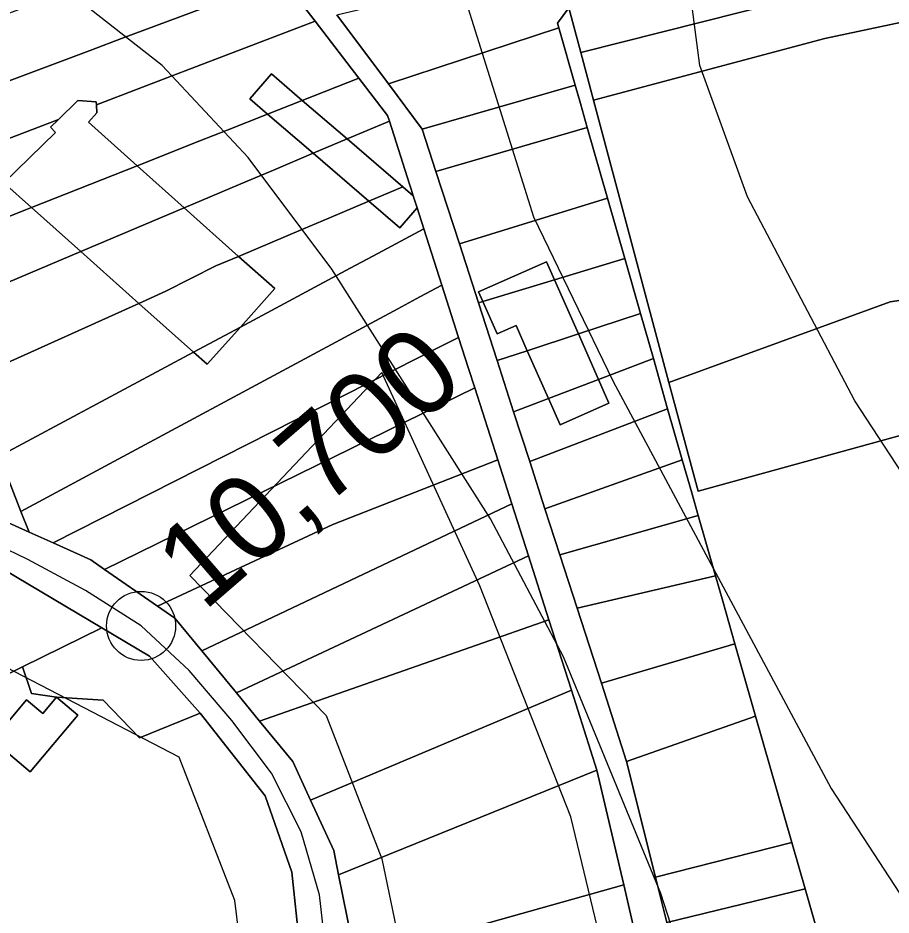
# Model space of a CAD drawing. Extents: x -510989 to -501240, y -1184665 to -1176098.
# Drawn here: x -509285.3 to -509152.5, y -1180014.3 to -1179877.8 of the extents above; entities that cross this region are included whole.
import ezdxf

# ---------------------------------------------------------------- set-up
doc = ezdxf.new("R2010")
doc.units = 0
for name, color, linetype in [('ostatni_plocha_x_manipulacni_plocha', 7, 'Continuous'), ('STAV_systematicke_odvodneni', 7, 'Continuous'), ('trasovani_toku', 7, 'Continuous'), ('trvaly_travni_porost', 7, 'Continuous'), ('vodni_plocha_x_vodni_tok_v_koryte_umelem', 7, 'Continuous'), ('vrstevnice_01', 7, 'Continuous'), ('vrstevnice_02', 7, 'Continuous'), ('zastavena_plocha_a_nadvori', 7, 'Continuous')]:
    doc.layers.add(name, color=color, linetype=linetype)

msp = doc.modelspace()

# ---------------------------------------------------------------- linework, layer by layer
at = {"layer": 'ostatni_plocha_x_manipulacni_plocha'}
for points in [[(-509245.12, -1179871.74), (-509269.59, -1179880.91), (-509274.08, -1179882.59), (-509299.47, -1179892.1), (-509300.3, -1179891.36), (-509292.23, -1179882.25), (-509294.72, -1179880.05), (-509282.51, -1179875.46), (-509277.9, -1179873.72), (-509251.28, -1179863.71)], [(-509194.72, -1179867.22), (-509198.47, -1179872.21), (-509201.5, -1179876.24), (-509203.25, -1179878.55), (-509203.04, -1179879.28), (-509228.95, -1179887.79), (-509236.79, -1179877.28)], [(-509240.13, -1179878.24), (-509262.69, -1179886.88), (-509267.04, -1179888.55), (-509273.41, -1179890.99), (-509273.44, -1179890.5), (-509276.22, -1179890.32), (-509279.16, -1179893.19), (-509338.41, -1179915.88), (-509354.67, -1179922.9), (-509366.26, -1179917.12), (-509299.47, -1179892.1), (-509274.08, -1179882.59), (-509269.59, -1179880.91), (-509245.12, -1179871.74)], [(-509262.69, -1179886.88), (-509240.13, -1179878.24), (-509233.49, -1179886.9), (-509242.08, -1179890.3), (-509246.77, -1179886.28), (-509250.04, -1179890.09), (-509247.36, -1179892.39), (-509253.51, -1179894.83), (-509257.67, -1179896.48), (-509267.21, -1179900.25), (-509274.62, -1179893.63), (-509273.33, -1179892.18), (-509273.41, -1179890.99), (-509267.04, -1179888.55)], [(-509228.95, -1179887.79), (-509203.04, -1179879.28), (-509200.54, -1179888), (-509223.83, -1179894.66)], [(-509242.08, -1179890.3), (-509233.49, -1179886.9), (-509229.09, -1179892.63), (-509228.82, -1179893.47), (-509235.24, -1179896.18)], [(-509200.54, -1179888), (-509199.75, -1179890.78), (-509198.71, -1179894.43), (-509221.74, -1179901.11), (-509223.83, -1179894.66)], [(-509253.51, -1179894.83), (-509247.36, -1179892.39), (-509240.41, -1179898.36), (-509246.46, -1179900.92), (-509250.44, -1179902.6), (-509260.03, -1179906.66), (-509267.21, -1179900.25), (-509257.67, -1179896.48)], [(-509279.16, -1179893.19), (-509280.4, -1179894.4), (-509279.63, -1179895.2), (-509287.49, -1179902.86), (-509283.28, -1179906.61), (-509298.86, -1179912.78), (-509345.31, -1179927.56), (-509354.67, -1179922.9), (-509338.41, -1179915.88)], [(-509235.24, -1179896.18), (-509228.82, -1179893.47), (-509225.76, -1179903.05), (-509225.52, -1179903.8), (-509225.19, -1179904.81), (-509226.76, -1179903.47)], [(-509221.74, -1179901.11), (-509198.71, -1179894.43), (-509195.63, -1179905.19), (-509218.17, -1179912.14)], [(-509246.46, -1179900.92), (-509240.41, -1179898.36), (-509231.92, -1179905.65), (-509238.01, -1179908.23), (-509241.87, -1179909.86), (-509251.76, -1179914.04), (-509260.03, -1179906.66), (-509250.44, -1179902.6)], [(-509238.01, -1179908.23), (-509231.92, -1179905.65), (-509227.22, -1179909.7), (-509224.6, -1179906.65), (-509223.58, -1179909.86), (-509231.33, -1179914.01), (-509234.78, -1179915.86), (-509251.49, -1179924.79), (-509246.27, -1179918.94), (-509251.76, -1179914.04), (-509241.87, -1179909.86)], [(-509218.17, -1179912.14), (-509195.63, -1179905.19), (-509193, -1179914.38), (-509203.69, -1179917.62), (-509204.89, -1179914.88), (-509215.25, -1179919.45), (-509214.6, -1179920.92), (-509215.27, -1179921.12)], [(-509298.86, -1179912.78), (-509283.28, -1179906.61), (-509275.78, -1179913.31), (-509296.5, -1179922.05), (-509334.69, -1179932.64), (-509345.31, -1179927.56)], [(-509231.33, -1179914.01), (-509223.58, -1179909.86), (-509220.84, -1179918.43), (-509224.16, -1179920.21), (-509227.51, -1179922.01), (-509284.89, -1179952.84), (-509288.21, -1179944.42), (-509258.64, -1179928.61), (-509256.56, -1179930.46), (-509251.49, -1179924.79), (-509234.78, -1179915.86)], [(-509275.78, -1179913.31), (-509266.94, -1179921.2), (-509289.06, -1179931.17), (-509314.67, -1179934.24), (-509322.46, -1179933.61), (-509334.69, -1179932.64), (-509296.5, -1179922.05)], [(-509203.69, -1179917.62), (-509193, -1179914.38), (-509190.61, -1179922.72), (-509200.06, -1179925.84)], [(-509224.16, -1179920.21), (-509220.84, -1179918.43), (-509218.29, -1179926.38), (-509220.83, -1179927.67), (-509280, -1179957.64), (-509283.64, -1179956), (-509284.89, -1179952.84), (-509227.51, -1179922.01)], [(-509266.94, -1179921.2), (-509258.64, -1179928.61), (-509288.21, -1179944.42), (-509287.28, -1179937.97), (-509311.6, -1179934.48), (-509314.67, -1179934.24), (-509289.06, -1179931.17)], [(-509215.27, -1179921.12), (-509214.6, -1179920.92), (-509212.43, -1179925.82), (-509209.53, -1179924.54), (-509207.83, -1179928.4), (-509212.43, -1179929.91)], [(-509200.06, -1179925.84), (-509190.61, -1179922.72), (-509188.65, -1179929.58), (-509196.99, -1179932.77)], [(-509220.83, -1179927.67), (-509218.29, -1179926.38), (-509216.78, -1179931.09), (-509215.83, -1179934.07), (-509272.16, -1179961.67), (-509274.23, -1179960.24), (-509280, -1179957.64)], [(-509212.43, -1179929.91), (-509207.83, -1179928.4), (-509204.61, -1179935.68), (-509209.91, -1179937.7)], [(-509196.99, -1179932.77), (-509188.65, -1179929.58), (-509186.47, -1179937.23), (-509207.46, -1179945.27), (-509209.91, -1179937.7), (-509204.61, -1179935.68), (-509202.85, -1179939.66), (-509195.4, -1179936.37)], [(-509311.6, -1179934.48), (-509287.28, -1179937.97), (-509288.21, -1179944.42), (-509284.89, -1179952.84), (-509283.64, -1179956), (-509308.5, -1179944.81)], [(-509212.33, -1179945), (-509237.41, -1179954.86), (-509264.12, -1179967.25), (-509272.16, -1179961.67), (-509215.83, -1179934.07)], [(-509186.47, -1179937.23), (-509184.24, -1179945.01), (-509205.14, -1179952.44), (-509207.46, -1179945.27)], [(-509210.2, -1179951.69), (-509257.36, -1179974.08), (-509261.47, -1179969.08), (-509264.12, -1179967.25), (-509237.41, -1179954.86), (-509212.33, -1179945)], [(-509184.24, -1179945.01), (-509182.8, -1179950.04), (-509181.82, -1179953.46), (-509202.87, -1179959.47), (-509205.14, -1179952.44)], [(-509308.37, -1179951.14), (-509303.03, -1179953.6), (-509289.24, -1179960.67), (-509272.59, -1179970.58), (-509284.66, -1179976.49), (-509289.12, -1179978.67), (-509294.14, -1179974.39), (-509290.6, -1179970.25), (-509297.99, -1179963.94), (-509301.31, -1179967.84), (-509303.11, -1179962.06)], [(-509207.66, -1179959.6), (-509252.09, -1179980.48), (-509257.36, -1179974.08), (-509210.2, -1179951.69)], [(-509202.87, -1179959.47), (-509181.82, -1179953.46), (-509179.19, -1179962.66), (-509200.25, -1179967.55)], [(-509204.54, -1179969.37), (-509248.57, -1179984.76), (-509252.09, -1179980.48), (-509207.66, -1179959.6)], [(-509179.19, -1179962.66), (-509178.09, -1179966.51), (-509176.23, -1179972.99), (-509196.56, -1179978.97), (-509200.25, -1179967.55)], [(-509272.59, -1179970.58), (-509265.34, -1179974.89), (-509257.62, -1179983.54), (-509266.85, -1179987.32), (-509272.39, -1179981.57), (-509279.49, -1179981.11), (-509283.26, -1179980.55), (-509284.66, -1179976.49)], [(-509201.12, -1179980.06), (-509240.8, -1179996.81), (-509243.51, -1179990.9), (-509248.57, -1179984.76), (-509204.54, -1179969.37)], [(-509196.56, -1179978.97), (-509176.23, -1179972.99), (-509173.08, -1179984), (-509192.71, -1179990.88)], [(-509283.26, -1179980.55), (-509279.49, -1179981.11), (-509281.57, -1179983.59), (-509284.05, -1179981.5), (-509289.22, -1179987.65), (-509283.48, -1179992.48), (-509276.22, -1179983.86), (-509279.49, -1179981.11), (-509272.39, -1179981.57), (-509266.85, -1179987.32), (-509257.62, -1179983.54), (-509247.71, -1179996.14), (-509243.68, -1180007.74), (-509242.47, -1180018.79), (-509284.8, -1180026.46), (-509292.2, -1180004.67), (-509287.42, -1179999.06), (-509291.8, -1179995.32), (-509294.36, -1179998.32), (-509297.64, -1179988.66), (-509294.4, -1179984.86), (-509289.12, -1179978.67), (-509284.66, -1179976.49)], [(-509197.23, -1179992.2), (-509236.54, -1180008.14), (-509237.28, -1180004.46), (-509240.8, -1179996.81), (-509201.12, -1179980.06)], [(-509192.71, -1179990.88), (-509173.08, -1179984), (-509167.57, -1180003.21), (-509188.32, -1180008.48)], [(-509197.23, -1179992.2), (-509193.16, -1180009.68), (-509233.9, -1180021.14), (-509236.54, -1180008.14)], [(-509188.32, -1180008.48), (-509167.57, -1180003.21), (-509165.54, -1180010.3), (-509186.6, -1180015.39)], [(-509191.41, -1180017.18), (-509234.79, -1180031.74), (-509233.9, -1180021.14), (-509193.16, -1180009.68)], [(-509186.6, -1180015.39), (-509165.54, -1180010.3), (-509163.91, -1180015.98), (-509185.17, -1180021.13)]]:
    msp.add_lwpolyline(points, close=True, dxfattribs=at)
for points in [[(-509191.41, -1180017.18), (-509193.16, -1180009.68), (-509197.23, -1179992.2), (-509201.12, -1179980.06), (-509204.54, -1179969.37), (-509207.66, -1179959.6), (-509210.2, -1179951.69), (-509212.33, -1179945), (-509215.83, -1179934.07), (-509216.78, -1179931.09), (-509218.29, -1179926.38), (-509220.84, -1179918.43), (-509223.58, -1179909.86), (-509224.6, -1179906.65), (-509225.19, -1179904.81), (-509225.52, -1179903.8), (-509225.76, -1179903.05), (-509228.82, -1179893.47), (-509229.09, -1179892.63), (-509233.49, -1179886.9), (-509240.13, -1179878.24), (-509245.12, -1179871.74)], [(-509236.79, -1179877.28), (-509228.95, -1179887.79), (-509223.83, -1179894.66), (-509221.74, -1179901.11), (-509218.17, -1179912.14), (-509215.27, -1179921.12), (-509212.43, -1179929.91), (-509209.91, -1179937.7), (-509207.46, -1179945.27), (-509205.14, -1179952.44), (-509202.87, -1179959.47), (-509200.25, -1179967.55), (-509196.56, -1179978.97), (-509192.71, -1179990.88), (-509188.32, -1180008.48), (-509186.6, -1180015.39)]]:
    msp.add_lwpolyline(points, dxfattribs=at)
at = {"layer": 'STAV_systematicke_odvodneni'}
for p, q in [((-509260.83, -1179990.26), (-509401.27, -1179917.35)), ((-509229.95, -1179931.73), (-509259.2, -1179962.6)), ((-509215.05, -1179964.19), (-509229.95, -1179931.73)), ((-509259.2, -1179962.6), (-509238.46, -1179983.89)), ((-509201.22, -1179999.32), (-509215.05, -1179964.19)), ((-509238.46, -1179983.89), (-509229.95, -1180005.71)), ((-509252.32, -1180012.08), (-509260.83, -1179990.26)), ((-509192.71, -1180034.44), (-509201.22, -1179999.32)), ((-509229.95, -1180005.71), (-509225.69, -1180026.46)), ((-509249.66, -1180033.9), (-509252.32, -1180012.08))]:
    msp.add_line(p, q, dxfattribs=at)
at = {"layer": 'trasovani_toku'}
for p, q in [((-509283.84, -1179960.17), (-509292.86, -1179955.85)), ((-509275.04, -1179964.9), (-509283.84, -1179960.17)), ((-509266.6, -1179970.27), (-509275.04, -1179964.9)), ((-509259.27, -1179977.07), (-509266.6, -1179970.27)), ((-509252.79, -1179984.69), (-509259.27, -1179977.07)), ((-509246.77, -1179992.68), (-509252.79, -1179984.69)), ((-509242.25, -1180001.59), (-509246.77, -1179992.68)), ((-509239.47, -1180011.2), (-509242.25, -1180001.59)), ((-509238.28, -1180021.13), (-509239.47, -1180011.2))]:
    msp.add_line(p, q, dxfattribs=at)
msp.add_circle((-509266.6, -1179970.27), 5.25, dxfattribs=at)
at = {"layer": 'trvaly_travni_porost'}
for points in [[(-508845.67, -1179783.53), (-508838.33, -1179784.55), (-508841.67, -1179793.79), (-508846.12, -1179793.66), (-508880.97, -1179803.77), (-508911.16, -1179814.59), (-508957.9, -1179828.6), (-509007.69, -1179840.45), (-509059.15, -1179850.43), (-509140.62, -1179868.2), (-509175.13, -1179876.85), (-509199.69, -1179883.02), (-509201.5, -1179876.24), (-509198.47, -1179872.21), (-509184.57, -1179868.62), (-509140.55, -1179857.26), (-509064.36, -1179840.59), (-509013.39, -1179831.15), (-509013.98, -1179827.94), (-508988.38, -1179820.46), (-508926.19, -1179805.83), (-508909.15, -1179801.32), (-508907.8, -1179803.82)], [(-508846.12, -1179793.66), (-508841.67, -1179793.79), (-508833.86, -1179797.81), (-508843.75, -1179801.39), (-508948.92, -1179833.69), (-509006.35, -1179847.7), (-509162.53, -1179880.9), (-509197.76, -1179890.25), (-509199.69, -1179883.02), (-509175.13, -1179876.85), (-509140.62, -1179868.2), (-509059.15, -1179850.43), (-509007.69, -1179840.45), (-508957.9, -1179828.6), (-508911.16, -1179814.59), (-508880.97, -1179803.77)], [(-508840.82, -1179809.47), (-508838.23, -1179816.59), (-508839.97, -1179824.86), (-508838.61, -1179839.98), (-508839.06, -1179845.97), (-508839.44, -1179851.07), (-508860.61, -1179856.49), (-508972.97, -1179893.55), (-508975.76, -1179885.1), (-509068.15, -1179907.03), (-509094.26, -1179909.58), (-509125.58, -1179916.86), (-509152.59, -1179920.98), (-509186.27, -1179933.21), (-509197.76, -1179890.25), (-509162.53, -1179880.9), (-509006.35, -1179847.7), (-508948.92, -1179833.69), (-508843.75, -1179801.39)], [(-508839.44, -1179851.07), (-508840.15, -1179860.69), (-508967.27, -1179901.72), (-509006.01, -1179912.33), (-509076.57, -1179927.87), (-509150.51, -1179941.15), (-509181.84, -1179949.78), (-509186.27, -1179933.21), (-509152.59, -1179920.98), (-509125.58, -1179916.86), (-509094.26, -1179909.58), (-509068.15, -1179907.03), (-508975.76, -1179885.1), (-508972.97, -1179893.55), (-508860.61, -1179856.49)]]:
    msp.add_lwpolyline(points, close=True, dxfattribs=at)
msp.add_lwpolyline([(-509163.91, -1180015.98), (-509165.54, -1180010.3), (-509167.57, -1180003.21), (-509173.08, -1179984), (-509176.23, -1179972.99), (-509178.09, -1179966.51), (-509179.19, -1179962.66), (-509181.82, -1179953.46), (-509182.8, -1179950.04), (-509184.24, -1179945.01), (-509186.47, -1179937.23), (-509188.65, -1179929.58), (-509190.61, -1179922.72), (-509193, -1179914.38), (-509195.63, -1179905.19), (-509198.71, -1179894.43), (-509199.75, -1179890.78), (-509200.54, -1179888), (-509203.04, -1179879.28), (-509203.25, -1179878.55), (-509201.5, -1179876.24), (-509199.69, -1179883.02), (-509197.76, -1179890.25), (-509186.27, -1179933.21), (-509181.84, -1179949.78), (-509150.51, -1179941.15)], dxfattribs=at)
at = {"layer": 'vodni_plocha_x_vodni_tok_v_koryte_umelem'}
for points in [[(-509308.5, -1179944.81), (-509283.64, -1179956), (-509280, -1179957.64), (-509274.23, -1179960.24), (-509272.16, -1179961.67), (-509264.12, -1179967.25), (-509261.47, -1179969.08), (-509257.36, -1179974.08), (-509252.09, -1179980.48), (-509248.57, -1179984.76), (-509243.51, -1179990.9), (-509240.8, -1179996.81), (-509237.28, -1180004.46), (-509236.54, -1180008.14), (-509233.9, -1180021.14)], [(-509242.47, -1180018.79), (-509243.68, -1180007.74), (-509247.71, -1179996.14), (-509257.62, -1179983.54), (-509265.34, -1179974.89), (-509272.59, -1179970.58), (-509289.24, -1179960.67)]]:
    msp.add_lwpolyline(points, dxfattribs=at)
at = {"layer": 'vrstevnice_01'}
for points in [[(-509102.5, -1180024), (-509126.59, -1179984), (-509158, -1179936), (-509174.31, -1179905), (-509181.59, -1179885), (-509184.31, -1179864), (-509184, -1179849), (-509182.31, -1179842), (-509180.59, -1179821), (-509181.81, -1179807), (-509187, -1179794), (-509194.81, -1179785), (-509205.91, -1179777), (-509230.41, -1179766), (-509254.69, -1179747), (-509275.5, -1179741), (-509305.69, -1179737), (-509320.19, -1179734), (-509338.31, -1179724), (-509350.81, -1179712), (-509367.09, -1179690), (-509378.31, -1179665)], [(-509177.5, -1180042), (-509187.5, -1180011), (-509202.31, -1179975), (-509213.41, -1179954), (-509237.59, -1179916), (-509250.31, -1179899), (-509263.41, -1179885), (-509282.5, -1179870), (-509327.59, -1179841), (-509352.19, -1179821), (-509378.5, -1179796), (-509418.81, -1179754), (-509424.19, -1179750), (-509432.91, -1179747)]]:
    msp.add_lwpolyline(points, dxfattribs=at)
at = {"layer": 'vrstevnice_02'}
msp.add_lwpolyline([(-509420.41, -1179467), (-509420, -1179484), (-509421.69, -1179496), (-509433.69, -1179532), (-509433.41, -1179535), (-509424.81, -1179542), (-509405.19, -1179713), (-509393.19, -1179727), (-509369, -1179750), (-509360, -1179756), (-509336.5, -1179767), (-509286.09, -1179784), (-509270.41, -1179790), (-509248.69, -1179806), (-509243.81, -1179811), (-509236.69, -1179822), (-509226, -1179847), (-509206.91, -1179908), (-509194.81, -1179933), (-509161.59, -1179995), (-509140.69, -1180027)], dxfattribs=at)
at = {"layer": 'zastavena_plocha_a_nadvori'}
for points in [[(-509246.77, -1179886.28), (-509242.08, -1179890.3), (-509247.36, -1179892.39), (-509250.04, -1179890.09)], [(-509273.44, -1179890.5), (-509273.41, -1179890.99), (-509273.33, -1179892.18), (-509274.62, -1179893.63), (-509267.21, -1179900.25), (-509283.28, -1179906.61), (-509287.49, -1179902.86), (-509279.63, -1179895.2), (-509280.4, -1179894.4), (-509279.16, -1179893.19), (-509276.22, -1179890.32)], [(-509247.36, -1179892.39), (-509242.08, -1179890.3), (-509235.24, -1179896.18), (-509240.41, -1179898.36)], [(-509240.41, -1179898.36), (-509235.24, -1179896.18), (-509226.76, -1179903.47), (-509231.92, -1179905.65)], [(-509283.28, -1179906.61), (-509267.21, -1179900.25), (-509260.03, -1179906.66), (-509275.78, -1179913.31)], [(-509225.19, -1179904.81), (-509224.6, -1179906.65), (-509227.22, -1179909.7), (-509231.92, -1179905.65), (-509226.76, -1179903.47)], [(-509275.78, -1179913.31), (-509260.03, -1179906.66), (-509251.76, -1179914.04), (-509255.21, -1179915.5), (-509262.82, -1179919.35), (-509266.94, -1179921.2)], [(-509255.21, -1179915.5), (-509251.76, -1179914.04), (-509246.27, -1179918.94), (-509251.49, -1179924.79), (-509258.64, -1179928.61), (-509266.94, -1179921.2), (-509262.82, -1179919.35)], [(-509204.89, -1179914.88), (-509203.69, -1179917.62), (-509214.6, -1179920.92), (-509215.25, -1179919.45)], [(-509214.6, -1179920.92), (-509203.69, -1179917.62), (-509200.06, -1179925.84), (-509207.83, -1179928.4), (-509209.53, -1179924.54), (-509212.43, -1179925.82)], [(-509258.64, -1179928.61), (-509251.49, -1179924.79), (-509256.56, -1179930.46)], [(-509207.83, -1179928.4), (-509200.06, -1179925.84), (-509196.99, -1179932.77), (-509204.61, -1179935.68)], [(-509204.61, -1179935.68), (-509196.99, -1179932.77), (-509195.4, -1179936.37), (-509202.85, -1179939.66)], [(-509279.49, -1179981.11), (-509276.22, -1179983.86), (-509283.48, -1179992.48), (-509289.22, -1179987.65), (-509284.05, -1179981.5), (-509281.57, -1179983.59)]]:
    msp.add_lwpolyline(points, close=True, dxfattribs=at)

# ---------------------------------------------------------------- texts
at = {"layer": 'trasovani_toku'}
msp.add_text('10,700', height=13, rotation=40.8066, dxfattribs=at).set_placement((-509257.09, -1179968.22))

doc.saveas('drawing.dxf')
